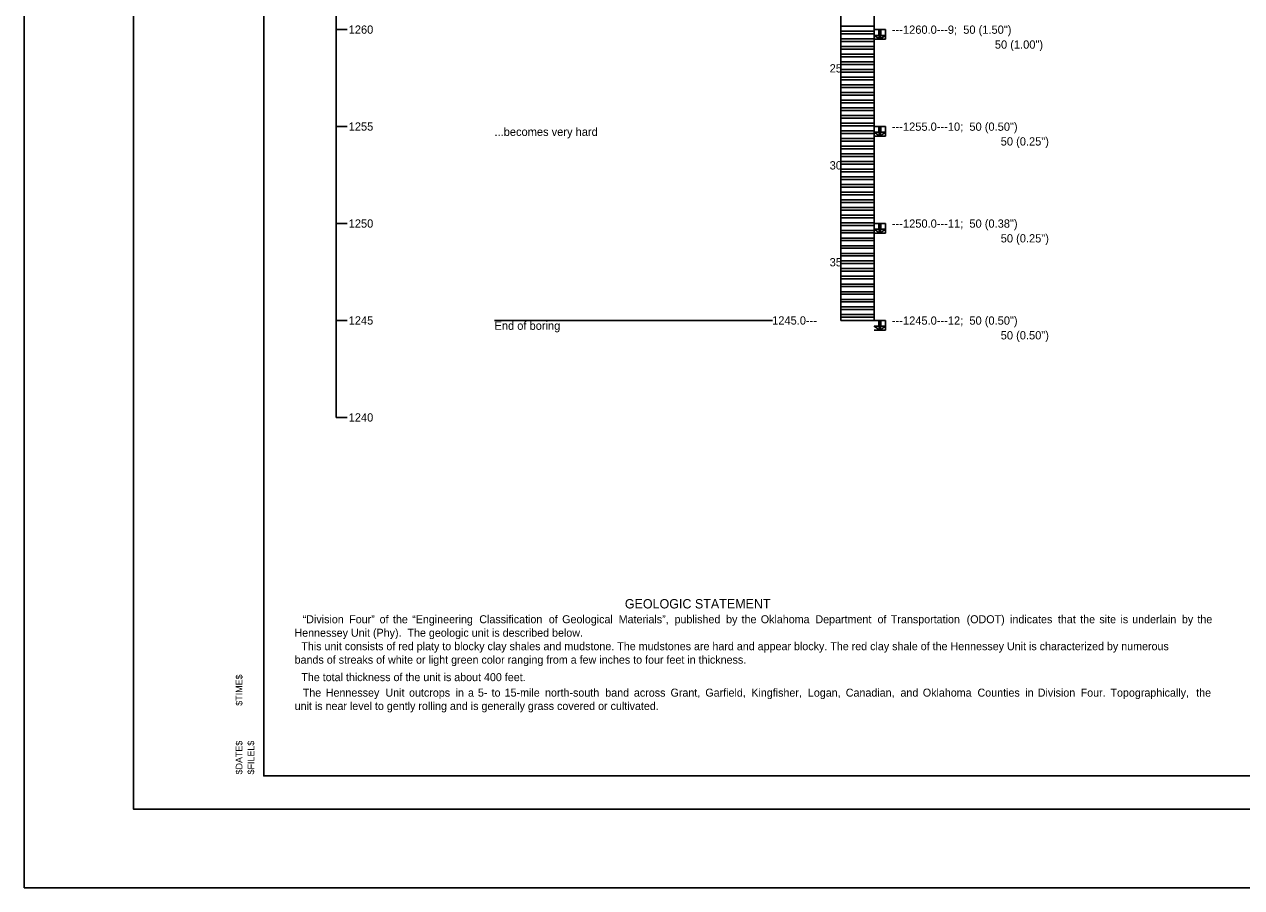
# Model space of a CAD drawing. Extents: x 7 to 126, y 24 to 56.
# Drawn here: x 6.62 to 24.87, y 29.97 to 42.91 of the extents above; entities that cross this region are included whole.
import ezdxf

# ---------------------------------------------------------------- set-up
doc = ezdxf.new("R2010")
doc.units = 0
for name, color, linetype in [('SHT_Plot_Shape_Full', 7, 'Continuous'), ('SHT_Plot_Shape_Half', 7, 'Continuous'), ('SHT_Plot_Stamp', 7, 'Continuous'), ('SHT_Sheet_Border', 7, 'Continuous'), ('Text', 7, 'Continuous')]:
    doc.layers.add(name, color=color, linetype=linetype)

# ---------------------------------------------------------------- blocks, each defined once
blk = doc.blocks.new('Stamp_Plot_Stamp')
at = {"layer": 'SHT_Plot_Stamp'}
for s, p in [('$TIME$', (1.695, 1.572)), ('$DATE$', (1.695, 0.542)), ('$FILEL$', (1.873, 0.542))]:
    blk.add_text(s, height=0.1, rotation=90, dxfattribs=at).set_placement(p)

msp = doc.modelspace()

# ---------------------------------------------------------------- linework, layer by layer
msp.add_line((11.298, 37.021), (11.298, 50.103))
for points in [[(18.866, 49.521), (18.866, 38.475)], [(19.366, 49.521), (19.366, 38.475)], [(18.866, 42.886), (19.366, 42.886)], [(11.298, 42.835), (11.464, 42.835)], [(18.866, 42.81), (19.366, 42.81)], [(18.866, 42.771), (19.366, 42.771)], [(19.366, 42.835), (19.533, 42.835)], [(19.533, 42.69), (19.533, 42.835)], [(18.866, 42.696), (19.366, 42.696)], [(18.866, 42.656), (19.366, 42.656)], [(18.866, 42.581), (19.366, 42.581)], [(18.866, 42.541), (19.366, 42.541)], [(19.366, 42.69), (19.533, 42.69)], [(18.866, 42.466), (19.366, 42.466)], [(18.866, 42.427), (19.366, 42.427)], [(18.866, 42.351), (19.366, 42.351)], [(18.866, 42.312), (19.366, 42.312)], [(18.866, 42.236), (19.366, 42.236)], [(18.866, 42.197), (19.366, 42.197)], [(18.866, 42.122), (19.366, 42.122)], [(18.866, 42.082), (19.366, 42.082)], [(18.866, 42.007), (19.366, 42.007)], [(18.866, 41.967), (19.366, 41.967)], [(18.866, 41.892), (19.366, 41.892)], [(18.866, 41.852), (19.366, 41.852)], [(18.866, 41.777), (19.366, 41.777)], [(18.866, 41.738), (19.366, 41.738)], [(18.866, 41.662), (19.366, 41.662)], [(18.866, 41.623), (19.366, 41.623)], [(18.866, 41.547), (19.366, 41.547)], [(18.866, 41.508), (19.366, 41.508)], [(18.866, 41.433), (19.366, 41.433)], [(11.298, 41.382), (11.464, 41.382)], [(18.866, 41.393), (19.366, 41.393)], [(18.866, 41.318), (19.366, 41.318)], [(18.866, 41.278), (19.366, 41.278)], [(19.366, 41.382), (19.533, 41.382)], [(19.533, 41.236), (19.533, 41.382)], [(18.866, 41.203), (19.366, 41.203)], [(18.866, 41.163), (19.366, 41.163)], [(18.866, 41.088), (19.366, 41.088)], [(19.366, 41.236), (19.533, 41.236)], [(18.866, 41.049), (19.366, 41.049)], [(18.866, 40.973), (19.366, 40.973)], [(18.866, 40.934), (19.366, 40.934)], [(18.866, 40.858), (19.366, 40.858)], [(18.866, 40.819), (19.366, 40.819)], [(18.866, 40.744), (19.366, 40.744)], [(18.866, 40.704), (19.366, 40.704)], [(18.866, 40.629), (19.366, 40.629)], [(18.866, 40.589), (19.366, 40.589)], [(18.866, 40.514), (19.366, 40.514)], [(18.866, 40.475), (19.366, 40.475)], [(18.866, 40.399), (19.366, 40.399)], [(18.866, 40.36), (19.366, 40.36)], [(18.866, 40.284), (19.366, 40.284)], [(18.866, 40.245), (19.366, 40.245)], [(18.866, 40.169), (19.366, 40.169)], [(18.866, 40.13), (19.366, 40.13)], [(18.866, 40.055), (19.366, 40.055)], [(18.866, 40.015), (19.366, 40.015)], [(11.298, 39.928), (11.464, 39.928)], [(18.866, 39.94), (19.366, 39.94)], [(18.866, 39.9), (19.366, 39.9)], [(18.866, 39.825), (19.366, 39.825)], [(18.866, 39.786), (19.366, 39.786)], [(19.366, 39.928), (19.533, 39.928)], [(19.366, 39.783), (19.533, 39.783)], [(19.533, 39.783), (19.533, 39.928)], [(18.866, 39.71), (19.366, 39.71)], [(18.866, 39.671), (19.366, 39.671)], [(18.866, 39.595), (19.366, 39.595)], [(18.866, 39.556), (19.366, 39.556)], [(18.866, 39.48), (19.366, 39.48)], [(18.866, 39.441), (19.366, 39.441)], [(18.866, 39.366), (19.366, 39.366)], [(18.866, 39.326), (19.366, 39.326)], [(18.866, 39.251), (19.366, 39.251)], [(18.866, 39.211), (19.366, 39.211)], [(18.866, 39.136), (19.366, 39.136)], [(18.866, 39.097), (19.366, 39.097)], [(18.866, 39.021), (19.366, 39.021)], [(18.866, 38.982), (19.366, 38.982)], [(18.866, 38.906), (19.366, 38.906)], [(18.866, 38.867), (19.366, 38.867)], [(18.866, 38.791), (19.366, 38.791)], [(18.866, 38.752), (19.366, 38.752)], [(18.866, 38.677), (19.366, 38.677)], [(18.866, 38.637), (19.366, 38.637)], [(18.866, 38.562), (19.366, 38.562)], [(18.866, 38.522), (19.366, 38.522)], [(11.298, 38.475), (11.464, 38.475)], [(13.672, 38.475), (17.839, 38.475)], [(18.866, 38.475), (19.366, 38.475)], [(19.366, 38.475), (19.533, 38.475)], [(19.366, 38.329), (19.533, 38.329)], [(19.533, 38.329), (19.533, 38.475)], [(11.298, 37.021), (11.464, 37.021)]]:
    msp.add_lwpolyline(points)
for points in [[(19.433, 42.748), (19.366, 42.748), (19.449, 42.69), (19.433, 42.748)], [(19.433, 42.748), (19.466, 42.748), (19.466, 42.835), (19.433, 42.748)], [(19.433, 42.748), (19.466, 42.835), (19.433, 42.835), (19.433, 42.748)], [(19.433, 42.748), (19.449, 42.69), (19.466, 42.748), (19.433, 42.748)], [(19.449, 42.69), (19.533, 42.748), (19.466, 42.748), (19.449, 42.69)], [(19.433, 41.295), (19.366, 41.295), (19.449, 41.236), (19.433, 41.295)], [(19.433, 41.295), (19.466, 41.295), (19.466, 41.382), (19.433, 41.295)], [(19.433, 41.295), (19.466, 41.382), (19.433, 41.382), (19.433, 41.295)], [(19.433, 41.295), (19.449, 41.236), (19.466, 41.295), (19.433, 41.295)], [(19.449, 41.236), (19.533, 41.295), (19.466, 41.295), (19.449, 41.236)], [(19.433, 39.841), (19.366, 39.841), (19.449, 39.783), (19.433, 39.841)], [(19.433, 39.841), (19.466, 39.841), (19.466, 39.928), (19.433, 39.841)], [(19.433, 39.841), (19.466, 39.928), (19.433, 39.928), (19.433, 39.841)], [(19.433, 39.841), (19.449, 39.783), (19.466, 39.841), (19.433, 39.841)], [(19.449, 39.783), (19.533, 39.841), (19.466, 39.841), (19.449, 39.783)], [(19.433, 38.388), (19.366, 38.388), (19.449, 38.329), (19.433, 38.388)], [(19.433, 38.388), (19.466, 38.388), (19.466, 38.475), (19.433, 38.388)], [(19.433, 38.388), (19.466, 38.475), (19.433, 38.475), (19.433, 38.388)], [(19.433, 38.388), (19.449, 38.329), (19.466, 38.388), (19.433, 38.388)], [(19.449, 38.329), (19.533, 38.388), (19.466, 38.388), (19.449, 38.329)]]:
    msp.add_lwpolyline(points, close=True)
at = {"layer": 'SHT_Plot_Shape_Full'}
msp.add_lwpolyline([(6.624, 53.971), (42.624, 53.971), (42.624, 29.971), (6.624, 29.971)], close=True, dxfattribs=at)
at = {"layer": 'SHT_Plot_Shape_Half'}
msp.add_lwpolyline([(8.262, 53.146), (42.262, 53.146), (42.262, 31.146), (8.262, 31.146)], close=True, dxfattribs=at)
at = {"layer": 'SHT_Sheet_Border'}
msp.add_lwpolyline([(10.212, 52.646), (41.712, 52.646), (41.712, 31.646), (10.212, 31.646)], close=True, dxfattribs=at)

# ---------------------------------------------------------------- block references
at = {"layer": 'SHT_Plot_Stamp'}
msp.add_blockref('Stamp_Plot_Stamp', (8.198, 31.127), dxfattribs=at)

# ---------------------------------------------------------------- texts
for s, p in [('1260', (11.486, 42.773)), ('---1260.0---9;  50 (1.50")', (19.63, 42.772)), ('50 (1.00")', (21.173, 42.549)), ('25', (18.696, 42.192)), ('1255', (11.486, 41.32)), ('---1255.0---10;  50 (0.50")', (19.63, 41.318)), ('...becomes very hard', (13.672, 41.241)), ('50 (0.25")', (21.261, 41.097)), ('30', (18.696, 40.738)), ('1250', (11.486, 39.866)), ('---1250.0---11;  50 (0.38")', (19.63, 39.865)), ('50 (0.25")', (21.261, 39.644)), ('35', (18.696, 39.285)), ('1245', (11.486, 38.413)), ('1245.0---', (17.834, 38.413)), ('---1245.0---12;  50 (0.50")', (19.63, 38.411)), ('End of boring', (13.672, 38.334)), ('50 (0.50")', (21.261, 38.19)), ('1240', (11.486, 36.959))]:
    msp.add_text(s, height=0.124).set_placement(p)
at = {"layer": 'Text'}
for s, height, p in [('GEOLOGIC STATEMENT', 0.14, (15.626, 34.157)), ('“Division', 0.12, (10.797, 33.935)), ('Four”', 0.12, (11.494, 33.935)), ('of', 0.12, (11.95, 33.935)), ('the', 0.12, (12.15, 33.935)), ('“Engineering', 0.12, (12.438, 33.935)), ('Classification', 0.12, (13.444, 33.935)), ('of', 0.12, (14.486, 33.935)), ('Geological', 0.12, (14.687, 33.935)), ('Materials”,', 0.12, (15.534, 33.935)), ('published', 0.12, (16.371, 33.935)), ('by', 0.12, (17.144, 33.935)), ('the', 0.12, (17.376, 33.935)), ('Oklahoma', 0.12, (17.664, 33.935)), ('Department', 0.12, (18.483, 33.935)), ('of', 0.12, (19.414, 33.935)), ('Transportation', 0.12, (19.614, 33.935)), ('(ODOT)', 0.12, (20.75, 33.935)), ('indicates', 0.12, (21.401, 33.935)), ('that', 0.12, (22.118, 33.935)), ('the', 0.12, (22.452, 33.935)), ('site', 0.12, (22.74, 33.935)), ('is', 0.12, (23.056, 33.935)), ('underlain', 0.12, (23.232, 33.935)), ('by', 0.12, (23.977, 33.935)), ('the ', 0.12, (24.209, 33.935)), ('Hennessey Unit (Phy).  The geologic unit is described below.', 0.12, (10.673, 33.733)), ('  This unit consists of red platy to blocky clay shales and mudstone. The mudstones are hard and appear blocky. The red clay shale of the Hennessey Unit is characterized by numerous ', 0.12, (10.687, 33.531)), ('bands of streaks of white or light green color ranging from a few inches to four feet in thickness.', 0.12, (10.676, 33.329)), ('  The total thickness of the unit is about 400 feet.', 0.12, (10.687, 33.067)), ('The', 0.12, (10.798, 32.835)), ('Hennessey', 0.12, (11.143, 32.835)), ('Unit', 0.12, (12.037, 32.835)), ('outcrops', 0.12, (12.391, 32.835)), ('in', 0.12, (13.089, 32.835)), ('a', 0.12, (13.275, 32.835)), ('5-', 0.12, (13.424, 32.835)), ('to', 0.12, (13.629, 32.835)), ('15-mile', 0.12, (13.824, 32.835)), ('north-south', 0.12, (14.43, 32.835)), ('band', 0.12, (15.333, 32.835)), ('across', 0.12, (15.762, 32.835)), ('Grant,', 0.12, (16.311, 32.835)), ('Garfield,', 0.12, (16.833, 32.835)), ('Kingfisher,', 0.12, (17.522, 32.835)), ('Logan,', 0.12, (18.37, 32.835)), ('Canadian,', 0.12, (18.938, 32.835)), ('and', 0.12, (19.758, 32.835)), ('Oklahoma', 0.12, (20.093, 32.835)), ('Counties', 0.12, (20.913, 32.835)), ('in', 0.12, (21.63, 32.835)), ('Division', 0.12, (21.816, 32.835)), ('Four.', 0.12, (22.459, 32.835)), ('Topographically,', 0.12, (22.906, 32.835)), ('the ', 0.12, (24.191, 32.835)), ('unit is near level to gently rolling and is generally grass covered or cultivated.  ', 0.12, (10.676, 32.635))]:
    msp.add_text(s, height=height, dxfattribs=at).set_placement(p)

doc.saveas('drawing.dxf')
